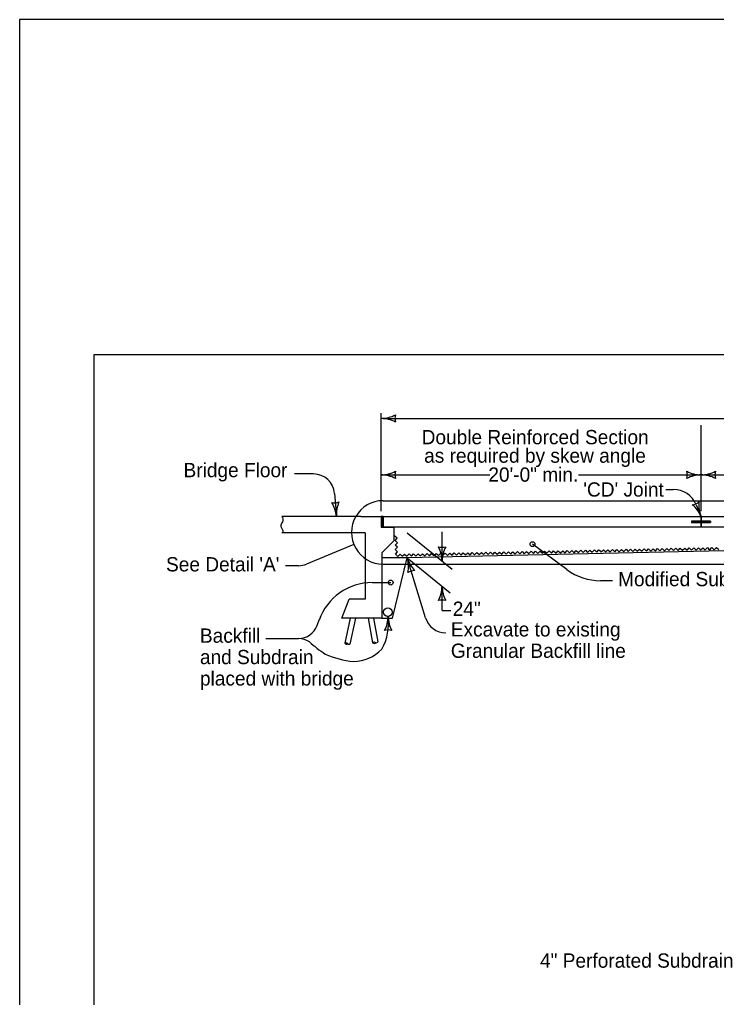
# Model space of a CAD drawing. Extents: x -2135039 to -2120895, y -2139150 to -2136566.
# Drawn here: x -2127839 to -2126862, y -2137937 to -2136566 of the extents above; entities that cross this region are included whole.
import ezdxf

# ---------------------------------------------------------------- set-up
doc = ezdxf.new("R2010")
doc.units = 0
for name, color, linetype in [('dsnDOTLogo', 7, 'Continuous'), ('dsnStdDimension', 7, 'Continuous'), ('dsnStdLabel', 7, 'Continuous'), ('dsnStdLineWork', 7, 'Continuous'), ('Level 1', 7, 'Continuous'), ('Level 2', 7, 'Continuous'), ('Level 3', 7, 'Continuous')]:
    doc.layers.add(name, color=color, linetype=linetype)

msp = doc.modelspace()

# ---------------------------------------------------------------- linework, layer by layer
at = {"layer": 'dsnDOTLogo'}
msp.add_lwpolyline([(-2127839, -2139150.4), (-2124495, -2139150.4), (-2124495, -2136566.4), (-2127839, -2136566.4)], close=True, dxfattribs=at)
at = {"layer": 'dsnStdDimension'}
for p, q in [((-2127332.3, -2137255.8), (-2127332.3, -2137118.2)), ((-2127329.4, -2137125.6), (-2125992.9, -2137125.6)), ((-2126883.9, -2137255.8), (-2126883.9, -2137135)), ((-2127329.4, -2137204.8), (-2127180, -2137204.8)), ((-2127055.9, -2137204.8), (-2126883.9, -2137204.8)), ((-2126883.9, -2137204.8), (-2126742.7, -2137204.8)), ((-2127295.7, -2137285.9), (-2127232.9, -2137337)), ((-2127246.9, -2137325.6), (-2127246.9, -2137284.5)), ((-2127295.7, -2137321.2), (-2127235.4, -2137370.3)), ((-2127246.9, -2137394.8), (-2127246.9, -2137360.9)), ((-2127246.9, -2137394.8), (-2127234.5, -2137394.8))]:
    msp.add_line(p, q, dxfattribs=at)
for centre, radius, start, end in [((-2127332.3, -2137082.9), 42.7, 270, 298.0725), ((-2127332.3, -2137168.4), 42.7, 61.9275, 90), ((-2127296.5, -2137125.6), 16.5, 162.2666, 197.7334), ((-2127332.3, -2137162.1), 42.7, 270, 298.0725), ((-2127296.5, -2137204.8), 16.5, 162.2666, 197.7334), ((-2126919.7, -2137204.8), 16.5, 342.2666, 17.7333), ((-2126883.9, -2137162.1), 42.7, 241.9275, 270), ((-2126919.7, -2137204.8), 16.5, 342.2666, 17.7333), ((-2126883.9, -2137162.1), 42.7, 241.9275, 270), ((-2126883.9, -2137162.1), 42.7, 270, 298.0725), ((-2126883.9, -2137162.1), 42.7, 270, 298.0725), ((-2126848, -2137204.8), 16.5, 162.2666, 197.7334), ((-2126848, -2137204.8), 16.5, 162.2666, 197.7334), ((-2127332.3, -2137247.6), 42.7, 61.9275, 90), ((-2126883.9, -2137247.6), 42.7, 90, 118.0725), ((-2126883.9, -2137247.6), 42.7, 90, 118.0725), ((-2126883.9, -2137247.6), 42.7, 61.9275, 90), ((-2126883.9, -2137247.6), 42.7, 61.9275, 90), ((-2127246.9, -2137289.8), 16.5, 252.2666, 287.7333), ((-2127289.6, -2137325.6), 42.7, 360, 28.0725), ((-2127246.9, -2137289.8), 16.5, 252.2666, 287.7333), ((-2127289.6, -2137325.6), 42.7, 360, 28.0725), ((-2127204.1, -2137325.6), 42.7, 151.9275, 180), ((-2127204.1, -2137325.6), 42.7, 151.9275, 180), ((-2127289.6, -2137360.9), 42.7, 331.9275, 360), ((-2127289.6, -2137360.9), 42.7, 331.9275, 360), ((-2127204.1, -2137360.9), 42.7, 180, 208.0725), ((-2127204.1, -2137360.9), 42.7, 180, 208.0725), ((-2127246.9, -2137396.8), 16.5, 72.2666, 107.7334), ((-2127246.9, -2137396.8), 16.5, 72.2666, 107.7334)]:
    msp.add_arc(centre, radius, start, end, dxfattribs=at)
at = {"layer": 'dsnStdLabel'}
for p, q in [((-2127427.1, -2137203.6), (-2127453.7, -2137203.6)), ((-2126933.1, -2137225.3), (-2126922.8, -2137225.3)), ((-2127397.5, -2137230.8), (-2127394.7, -2137263.3)), ((-2127397.5, -2137230.8), (-2127394.7, -2137263.3)), ((-2127329.4, -2137241), (-2126526.2, -2137241)), ((-2126890.8, -2137246.6), (-2126883.9, -2137263.3)), ((-2127370.5, -2137302.6), (-2127436.7, -2137329.9)), ((-2127072.1, -2137337.6), (-2127120.1, -2137302)), ((-2127270.1, -2137405.1), (-2127295.7, -2137321.2)), ((-2127448.1, -2137332.2), (-2127466.3, -2137332.2)), ((-2127329.4, -2137330.1), (-2126526.2, -2137330.1)), ((-2127344.7, -2137355.8), (-2127318.9, -2137355.8)), ((-2127008, -2137353.2), (-2127024.9, -2137353.2)), ((-2127421.9, -2137415.9), (-2127419.2, -2137408.3)), ((-2127493.7, -2137434.2), (-2127448, -2137434.2))]:
    msp.add_line(p, q, dxfattribs=at)
for centre in [(-2127120.1, -2137302), (-2127318.9, -2137355.8)]:
    msp.add_circle(centre, 3.46, dxfattribs=at)
for centre, radius, start, end in [((-2127427.1, -2137233.3), 29.7, 4.9696, 90), ((-2126922.8, -2137259.9), 34.6, 22.5907, 90), ((-2127329.4, -2137285.5), 44.5, 89.9996, 270), ((-2127397.8, -2137227.6), 16.5, 257.2356, 292.7023), ((-2127397.8, -2137227.6), 16.5, 257.2356, 292.7023), ((-2127437.3, -2137267), 42.7, 4.969, 33.0415), ((-2127437.3, -2137267), 42.7, 4.969, 33.0415), ((-2127352.1, -2137259.6), 42.7, 156.8965, 184.969), ((-2127352.1, -2137259.6), 42.7, 156.8965, 184.969), ((-2126897.6, -2137230.2), 16.5, 274.8585, 310.3252), ((-2126897.6, -2137230.2), 16.5, 274.8585, 310.3252), ((-2126923.3, -2137279.7), 42.7, 22.5918, 50.6643), ((-2126923.3, -2137279.7), 42.7, 22.5918, 50.6643), ((-2126844.4, -2137246.8), 42.7, 174.5193, 202.5918), ((-2126844.4, -2137246.8), 42.7, 174.5193, 202.5918), ((-2127254.8, -2137308.7), 42.7, 196.9513, 225.0238), ((-2127336.6, -2137333.6), 42.7, 348.8788, 16.9513), ((-2127254.8, -2137308.7), 42.7, 196.9513, 225.0238), ((-2127336.6, -2137333.6), 42.7, 348.8788, 16.9513), ((-2127448.1, -2137302.5), 29.7, 270, 292.4496), ((-2127024.9, -2137274), 79.2, 233.4243, 270), ((-2127285.3, -2137355.5), 16.5, 89.2179, 124.6846), ((-2127285.3, -2137355.5), 16.5, 89.2179, 124.6846), ((-2127344.7, -2137435), 79.2, 90, 160.3012), ((-2127393.3, -2137413.9), 71.3, 330.5092, 8.5915), ((-2127364.9, -2137403), 42.5, 331.8196, 359.892), ((-2127279.9, -2137403.1), 42.5, 179.892, 207.9645), ((-2127241.7, -2137396.5), 29.7, 196.9535, 270), ((-2127448, -2137406.5), 27.7, 270, 340.3019), ((-2127322.5, -2137438.7), 16.4, 72.1587, 107.6254), ((-2127448, -2137462), 27.7, 56.8248, 90), ((-2127321.6, -2137318.8), 163.6, 227.1442, 236.9942), ((-2127361.7, -2137348.2), 118.5, 245.5915, 265.546), ((-2127371.3, -2137411.3), 55, 270.3325, 316.7198)]:
    msp.add_arc(centre, radius, start, end, dxfattribs=at)
at = {"layer": 'dsnStdLineWork'}
for p, q in [((-2127332.3, -2137266.6), (-2127329.4, -2137263.7)), ((-2127332.3, -2137264.5), (-2127331.5, -2137263.7)), ((-2127332.3, -2137268.7), (-2127329.4, -2137265.8)), ((-2127332.3, -2137270.8), (-2127329.4, -2137267.9)), ((-2127332.3, -2137272.9), (-2127329.4, -2137270)), ((-2127332.3, -2137275), (-2127329.4, -2137272.1)), ((-2127332.3, -2137277.1), (-2127329.4, -2137274.2)), ((-2127332.3, -2137278.2), (-2127314.5, -2137278.2)), ((-2127331.3, -2137278.2), (-2127329.4, -2137276.3))]:
    msp.add_line(p, q, dxfattribs=at)
for points in [[(-2127310.6, -2137317.6), (-2127312.3, -2137316), (-2127309.2, -2137312.7), (-2127312.4, -2137309.6), (-2127309.3, -2137306.4), (-2127312.6, -2137303.3), (-2127309.5, -2137300), (-2127312.7, -2137297), (-2127309.6, -2137293.7), (-2127312.9, -2137290.6), (-2127312.7, -2137290.5)], [(-2127101.5, -2137313.2), (-2127099.9, -2137314.7), (-2127096.8, -2137311.5), (-2127093.6, -2137314.6), (-2127090.5, -2137311.3), (-2127087.2, -2137314.4), (-2127084.1, -2137311.2), (-2127080.9, -2137314.3), (-2127077.8, -2137311.1), (-2127074.5, -2137314.2), (-2127071.4, -2137310.9), (-2127068.2, -2137314), (-2127065.1, -2137310.8), (-2127061.9, -2137313.9), (-2127058.8, -2137310.7), (-2127055.5, -2137313.8), (-2127052.4, -2137310.5), (-2127049.2, -2137313.6), (-2127046.1, -2137310.4), (-2127042.9, -2137313.5), (-2127039.8, -2137310.2), (-2127036.5, -2137313.4), (-2127033.4, -2137310.1), (-2127030.2, -2137313.2), (-2127027.1, -2137310), (-2127025.5, -2137311.5)], [(-2127025.5, -2137311.5), (-2127023.9, -2137313.1), (-2127020.8, -2137309.8), (-2127017.5, -2137312.9), (-2127014.4, -2137309.7), (-2127011.2, -2137312.8), (-2127008.1, -2137309.6), (-2127004.9, -2137312.7), (-2127001.8, -2137309.4), (-2126998.5, -2137312.5), (-2126995.4, -2137309.3), (-2126992.2, -2137312.4), (-2126989.1, -2137309.2), (-2126985.9, -2137312.3), (-2126982.8, -2137309), (-2126979.5, -2137312.1), (-2126976.4, -2137308.9), (-2126973.2, -2137312), (-2126970.1, -2137308.8), (-2126966.9, -2137311.9), (-2126963.8, -2137308.6), (-2126960.5, -2137311.7), (-2126957.4, -2137308.5), (-2126954.2, -2137311.6), (-2126951.1, -2137308.4), (-2126949.5, -2137309.9)], [(-2126949.5, -2137309.9), (-2126947.9, -2137311.5), (-2126944.8, -2137308.2), (-2126941.5, -2137311.3), (-2126938.4, -2137308.1), (-2126935.2, -2137311.2), (-2126932.1, -2137307.9), (-2126928.9, -2137311), (-2126925.8, -2137307.8), (-2126922.5, -2137310.9), (-2126919.4, -2137307.7), (-2126916.2, -2137310.8), (-2126913.1, -2137307.5), (-2126909.8, -2137310.6), (-2126906.7, -2137307.4), (-2126903.5, -2137310.5), (-2126900.4, -2137307.3), (-2126897.2, -2137310.4), (-2126894.1, -2137307.1), (-2126890.8, -2137310.2), (-2126887.7, -2137307), (-2126884.5, -2137310.1), (-2126881.4, -2137306.9), (-2126878.2, -2137310), (-2126875.1, -2137306.7), (-2126873.5, -2137308.3)], [(-2126873.5, -2137308.3), (-2126871.8, -2137309.8), (-2126868.7, -2137306.6), (-2126865.5, -2137309.7), (-2126862.4, -2137306.5), (-2126859.2, -2137309.6)], [(-2127312.2, -2137316.1), (-2127312.2, -2137316.1), (-2127308.9, -2137319.2), (-2127305.8, -2137315.9), (-2127302.6, -2137319), (-2127299.5, -2137315.8), (-2127296.3, -2137318.9), (-2127293.2, -2137315.7), (-2127289.9, -2137318.8), (-2127286.8, -2137315.5), (-2127283.6, -2137318.6), (-2127280.5, -2137315.4), (-2127277.3, -2137318.5), (-2127274.2, -2137315.3), (-2127270.9, -2137318.4), (-2127267.8, -2137315.1), (-2127264.6, -2137318.2), (-2127261.5, -2137315), (-2127258.2, -2137318.1), (-2127255.1, -2137314.9), (-2127253.5, -2137316.4)], [(-2127253.5, -2137316.4), (-2127251.9, -2137318), (-2127248.8, -2137314.7), (-2127245.6, -2137317.8), (-2127242.5, -2137314.6), (-2127239.2, -2137317.7), (-2127236.1, -2137314.5), (-2127232.9, -2137317.5), (-2127229.8, -2137314.3), (-2127226.6, -2137317.4), (-2127223.5, -2137314.2), (-2127220.2, -2137317.3), (-2127217.1, -2137314), (-2127213.9, -2137317.1), (-2127210.8, -2137313.9), (-2127207.6, -2137317), (-2127204.5, -2137313.8), (-2127201.2, -2137316.9), (-2127198.1, -2137313.6), (-2127194.9, -2137316.7), (-2127191.8, -2137313.5), (-2127188.6, -2137316.6), (-2127185.5, -2137313.4), (-2127182.2, -2137316.5), (-2127179.1, -2137313.2), (-2127177.5, -2137314.8)], [(-2127177.5, -2137314.8), (-2127175.9, -2137316.3), (-2127172.8, -2137313.1), (-2127169.6, -2137316.2), (-2127166.5, -2137313), (-2127163.2, -2137316.1), (-2127160.1, -2137312.8), (-2127156.9, -2137315.9), (-2127153.8, -2137312.7), (-2127150.6, -2137315.8), (-2127147.5, -2137312.6), (-2127144.2, -2137315.7), (-2127141.1, -2137312.4), (-2127137.9, -2137315.5), (-2127134.8, -2137312.3), (-2127131.6, -2137315.4), (-2127128.5, -2137312.1), (-2127125.2, -2137315.2), (-2127122.1, -2137312), (-2127118.9, -2137315.1), (-2127115.8, -2137311.9), (-2127112.6, -2137315), (-2127109.5, -2137311.7), (-2127106.2, -2137314.8), (-2127103.1, -2137311.6), (-2127101.5, -2137313.2)]]:
    msp.add_lwpolyline(points, dxfattribs=at)
at = {"layer": 'Level 1'}
msp.add_lwpolyline([(-2127734.5, -2137035.9), (-2124599.5, -2137035.9), (-2124599.5, -2139045.9), (-2127734.5, -2139045.9)], close=True, dxfattribs=at)
at = {"layer": 'Level 2'}
for p, q in [((-2127360.5, -2137263.3), (-2127471.2, -2137263.3)), ((-2127360.5, -2137263.3), (-2127332.3, -2137263.3)), ((-2127332.3, -2137263.3), (-2127332.3, -2137278.2)), ((-2127329.4, -2137263.3), (-2127332.3, -2137263.3)), ((-2127329.4, -2137263.7), (-2127332.3, -2137263.7)), ((-2127329.4, -2137263.3), (-2127329.4, -2137278.2)), ((-2127329.4, -2137263.3), (-2126174.4, -2137263.3)), ((-2126883.9, -2137263.3), (-2126883.9, -2137269.8)), ((-2126188.1, -2137278.1), (-2127329.4, -2137278.1)), ((-2127314.5, -2137278.2), (-2127314.5, -2137297.4)), ((-2126897.2, -2137269.8), (-2126870.5, -2137269.8)), ((-2126897.2, -2137271.6), (-2126870.5, -2137271.6)), ((-2126883.9, -2137278.1), (-2126883.9, -2137271.6)), ((-2126870.5, -2137269.8), (-2126870.5, -2137271.6)), ((-2127354.6, -2137286.2), (-2127471.2, -2137286.2)), ((-2127354.6, -2137286.2), (-2127354.6, -2137379.1)), ((-2126178.5, -2137295.9), (-2127295.7, -2137321.2)), ((-2127314.5, -2137297.4), (-2127331.3, -2137314.2)), ((-2127331.3, -2137314.2), (-2127331.3, -2137405.8)), ((-2127295.7, -2137321.2), (-2127331.3, -2137321.2)), ((-2127316.4, -2137405.8), (-2127295.7, -2137321.2)), ((-2127387.3, -2137405.8), (-2127377, -2137379.1)), ((-2127354.6, -2137379.1), (-2127377, -2137379.1)), ((-2127331.3, -2137405.8), (-2127387.3, -2137405.8)), ((-2127375.8, -2137405.8), (-2127383.3, -2137440.6)), ((-2127368.2, -2137405.8), (-2127376.1, -2137442.2)), ((-2127350.5, -2137405.8), (-2127344.2, -2137440.2)), ((-2127343, -2137405.8), (-2127336.9, -2137438.8)), ((-2127331.3, -2137405.8), (-2127316.4, -2137405.8))]:
    msp.add_line(p, q, dxfattribs=at)
msp.add_circle((-2127322.8, -2137397.3), 5.94, dxfattribs=at)
for points in [[(-2127471.2, -2137263.3), (-2127470, -2137269.2), (-2127473, -2137275.2), (-2127470.2, -2137282.9), (-2127470.6, -2137286.2)], [(-2127383.3, -2137440.6), (-2127380.2, -2137440.3), (-2127378.5, -2137442), (-2127376.1, -2137442.2)], [(-2127383.3, -2137440.6), (-2127381.2, -2137442.1), (-2127378.8, -2137441.9)], [(-2127344.2, -2137440.2), (-2127341.5, -2137439), (-2127338.7, -2137440.2), (-2127336.9, -2137438.8)], [(-2127344.2, -2137440.2), (-2127341.5, -2137441.1), (-2127339.5, -2137440.2)]]:
    msp.add_spline(points, degree=3, dxfattribs=at)
at = {"layer": 'Level 3'}
for p, q in [((-2127329.4, -2137278.2), (-2127329.4, -2137263.3)), ((-2127329.4, -2137263.3), (-2126883.9, -2137263.3)), ((-2126883.9, -2137263.3), (-2126883.9, -2137269.8)), ((-2126883.9, -2137269.8), (-2126883.9, -2137263.3)), ((-2126883.9, -2137263.3), (-2126527.5, -2137263.3)), ((-2127314.5, -2137278.2), (-2127329.4, -2137278.2)), ((-2127292.2, -2137278.1), (-2127314.5, -2137278.2)), ((-2126883.9, -2137278.1), (-2127292.2, -2137278.1)), ((-2126883.9, -2137269.8), (-2126897.2, -2137269.8)), ((-2126897.2, -2137269.8), (-2126897.2, -2137271.6)), ((-2126870.5, -2137269.8), (-2126897.2, -2137269.8)), ((-2126897.2, -2137269.8), (-2126883.9, -2137269.8)), ((-2126897.2, -2137269.8), (-2126897.2, -2137271.6)), ((-2126897.2, -2137271.6), (-2126883.9, -2137271.6)), ((-2126883.9, -2137271.6), (-2126883.9, -2137278.1)), ((-2126883.9, -2137278.1), (-2126883.9, -2137271.6)), ((-2126883.9, -2137271.6), (-2126870.5, -2137271.6)), ((-2126527.5, -2137278.1), (-2126883.9, -2137278.1)), ((-2126870.5, -2137271.6), (-2126870.5, -2137269.8))]:
    msp.add_line(p, q, dxfattribs=at)

# ---------------------------------------------------------------- texts
at = {"layer": 'dsnStdDimension'}
for s, p in [('Double Reinforced Section', (-2127275.5, -2137161.9)), ('as required by skew angle', (-2127272, -2137187.8)), ('20\'-0" min.', (-2127182, -2137214.4)), ('24"', (-2127231.9, -2137402.5))]:
    msp.add_text(s, height=20, dxfattribs=at).set_placement(p)
at = {"layer": 'dsnStdLabel'}
for s, p in [('Bridge Floor', (-2127609.2, -2137208.1)), ("'CD' Joint", (-2127048.9, -2137235.3)), ("See Detail 'A'", (-2127633.7, -2137340.2)), ('Modified Subbase', (-2127000.2, -2137360.9)), ('Backfill', (-2127586.2, -2137440.2)), ('Excavate to existing', (-2127234.6, -2137431.4)), ('Granular Backfill line', (-2127234.6, -2137461.4)), ('and Subdrain', (-2127586.2, -2137470.2)), ('placed with bridge', (-2127586.2, -2137500.2)), ('4" Perforated Subdrain', (-2127109.6, -2137895.8))]:
    msp.add_text(s, height=20, dxfattribs=at).set_placement(p)

doc.saveas('drawing.dxf')
